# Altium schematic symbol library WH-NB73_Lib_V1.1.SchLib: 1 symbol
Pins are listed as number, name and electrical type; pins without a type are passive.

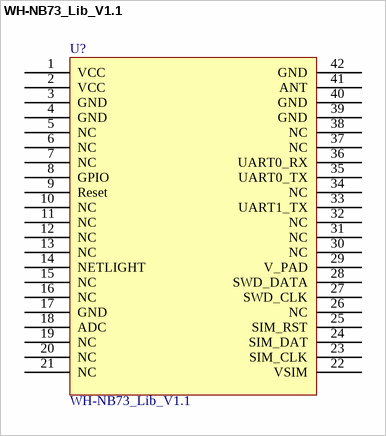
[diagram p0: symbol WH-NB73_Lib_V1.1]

## WH-NB73_Lib_V1.1
designator U?
pins: 1 VCC, 2 VCC, 3 GND, 4 GND, 5 NC, 6 NC, 7 NC, 8 GPIO, 9 Reset, 10 NC, 11 NC, 12 NC, 13 NC, 14 NETLIGHT, 15 NC, 16 NC, 17 GND, 18 ADC, 19 NC, 20 NC, 21 NC, 22 VSIM, 23 SIM_CLK, 24 SIM_DAT, 25 SIM_RST, 26 NC, 27 SWD_CLK, 28 SWD_DATA, 29 V_PAD, 30 NC, 31 NC, 32 NC, 33 UART1_TX, 34 NC, 35 UART0_TX, 36 UART0_RX, 37 NC, 38 NC, 39 GND, 40 GND, 41 ANT, 42 GND
2 alternate drawings of the same symbol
